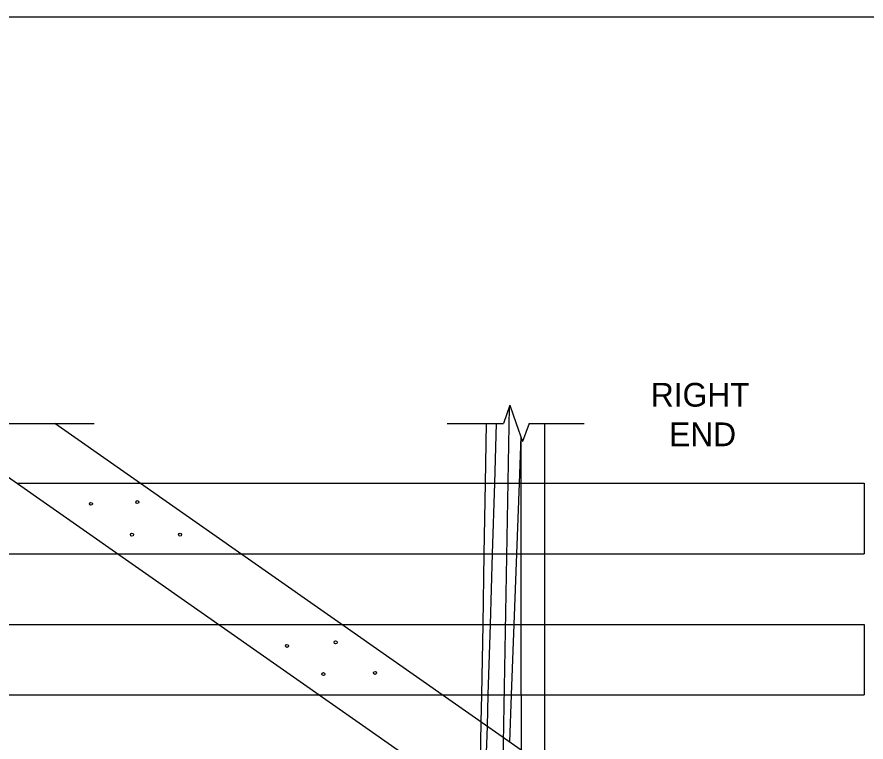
# Model space of a CAD drawing. Extents: x 49991.4 to 50021, y 49987.6 to 50011.4.
# Drawn here: x 50012.715 to 50014.862, y 49997.167 to 49998.999 of the extents above; entities that cross this region are included whole.
import ezdxf

# ---------------------------------------------------------------- set-up
doc = ezdxf.new("R2010")
doc.units = 0
for name, color, linetype in [('Level 1', 7, 'Continuous'), ('Level 2', 7, 'Continuous'), ('Level 4', 7, 'Continuous'), ('Level 6', 7, 'Continuous')]:
    doc.layers.add(name, color=color, linetype=linetype)

msp = doc.modelspace()

# ---------------------------------------------------------------- linework, layer by layer
at = {"layer": 'Level 1'}
for p, q in [((50012.4994, 49997.9721), (50014.4981, 49996.5727)), ((50014.6004, 49996.7189), (50012.8106, 49997.9721)), ((50013.8999, 49997.821), (50013.9026, 49997.9721)), ((50013.9271, 49997.9721), (50013.9225, 49997.821)), ((50014.0492, 49997.9721), (50014.0492, 49997.821)), ((50013.9854, 49997.821), (50013.9897, 49997.9377)), ((50013.9897, 49997.821), (50013.9897, 49997.9377)), ((50013.0264, 49997.821), (50014.8571, 49997.821)), ((50014.8571, 49997.821), (50014.8571, 49997.6425)), ((50009.1361, 49997.6425), (50012.9702, 49997.6425)), ((50013.2813, 49997.6425), (50014.8571, 49997.6425)), ((50013.8935, 49997.464), (50013.8967, 49997.6425)), ((50013.917, 49997.6425), (50013.9116, 49997.464)), ((50013.9721, 49997.464), (50013.9787, 49997.6425)), ((50013.9897, 49997.464), (50013.9897, 49997.6425)), ((50014.0492, 49997.6425), (50014.0492, 49997.464)), ((50009.1361, 49997.464), (50013.2251, 49997.464)), ((50013.5363, 49997.464), (50014.8571, 49997.464)), ((50014.8571, 49997.464), (50014.8571, 49997.2855)), ((50009.1361, 49997.2855), (50013.48, 49997.2855)), ((50013.7912, 49997.2855), (50014.8571, 49997.2855)), ((50013.8891, 49997.217), (50013.8903, 49997.2855)), ((50013.9061, 49997.2855), (50013.9037, 49997.2067)), ((50013.961, 49997.1666), (50013.9654, 49997.2855)), ((50013.9897, 49997.2855), (50013.9897, 49997.1465)), ((50014.0492, 49997.2855), (50014.0492, 49997.1048))]:
    msp.add_line(p, q, dxfattribs=at)
msp.add_lwpolyline([(49999.3835, 49998.9992), (50016.7501, 49998.9992), (50016.7501, 49987.7988), (49999.3835, 49987.7988)], close=True, dxfattribs=at)
for centre in [(50012.9024, 49997.7686), (50013.0195, 49997.7731), (50013.006, 49997.6908), (50013.1276, 49997.6908), (50013.521, 49997.4186), (50013.3979, 49997.4096), (50013.4899, 49997.3382), (50013.6205, 49997.3412)]:
    msp.add_circle(centre, 0.00374, dxfattribs=at)
at = {"layer": 'Level 4'}
for p, q in [((50013.9595, 49998.0128), (50013.9302, 49996.3317)), ((50012.7154, 49997.821), (50013.0264, 49997.821)), ((50013.8967, 49997.6425), (50013.8999, 49997.821)), ((50013.9225, 49997.821), (50013.917, 49997.6425)), ((50013.9787, 49997.6425), (50013.9854, 49997.821)), ((50013.9897, 49997.6425), (50013.9897, 49997.821)), ((50014.0492, 49997.821), (50014.0492, 49997.6425)), ((50012.9702, 49997.6425), (50013.2813, 49997.6425)), ((50013.2251, 49997.464), (50013.5363, 49997.464)), ((50013.8903, 49997.2855), (50013.8935, 49997.464)), ((50013.9116, 49997.464), (50013.9061, 49997.2855)), ((50013.9654, 49997.2855), (50013.9721, 49997.464)), ((50013.9897, 49997.2855), (50013.9897, 49997.464)), ((50014.0492, 49997.464), (50014.0492, 49997.2855)), ((50013.48, 49997.2855), (50013.7912, 49997.2855)), ((50013.8839, 49996.9285), (50013.8891, 49997.217)), ((50013.9037, 49997.2067), (50013.8952, 49996.9285))]:
    msp.add_line(p, q, dxfattribs=at)
at = {"layer": 'Level 6'}
for p, q in [((50013.9613, 49998.0178), (50013.9451, 49997.9721)), ((50013.9613, 49998.0178), (50013.9775, 49997.9721)), ((50012.6874, 49997.9721), (50012.9106, 49997.9721)), ((50013.8026, 49997.9721), (50013.9451, 49997.9721)), ((50013.9775, 49997.9721), (50013.9937, 49997.9264)), ((50014.0099, 49997.9721), (50013.9937, 49997.9264)), ((50014.0099, 49997.9721), (50014.1492, 49997.9721))]:
    msp.add_line(p, q, dxfattribs=at)

# ---------------------------------------------------------------- texts
at = {"layer": 'Level 2'}
for s, p in [('RIGHT', (50014.3178, 49998.0143)), ('END', (50014.3641, 49997.9143))]:
    msp.add_text(s, height=0.06, dxfattribs=at).set_placement(p)

doc.saveas('drawing.dxf')
